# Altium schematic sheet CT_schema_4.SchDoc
size 235 x 238 mm
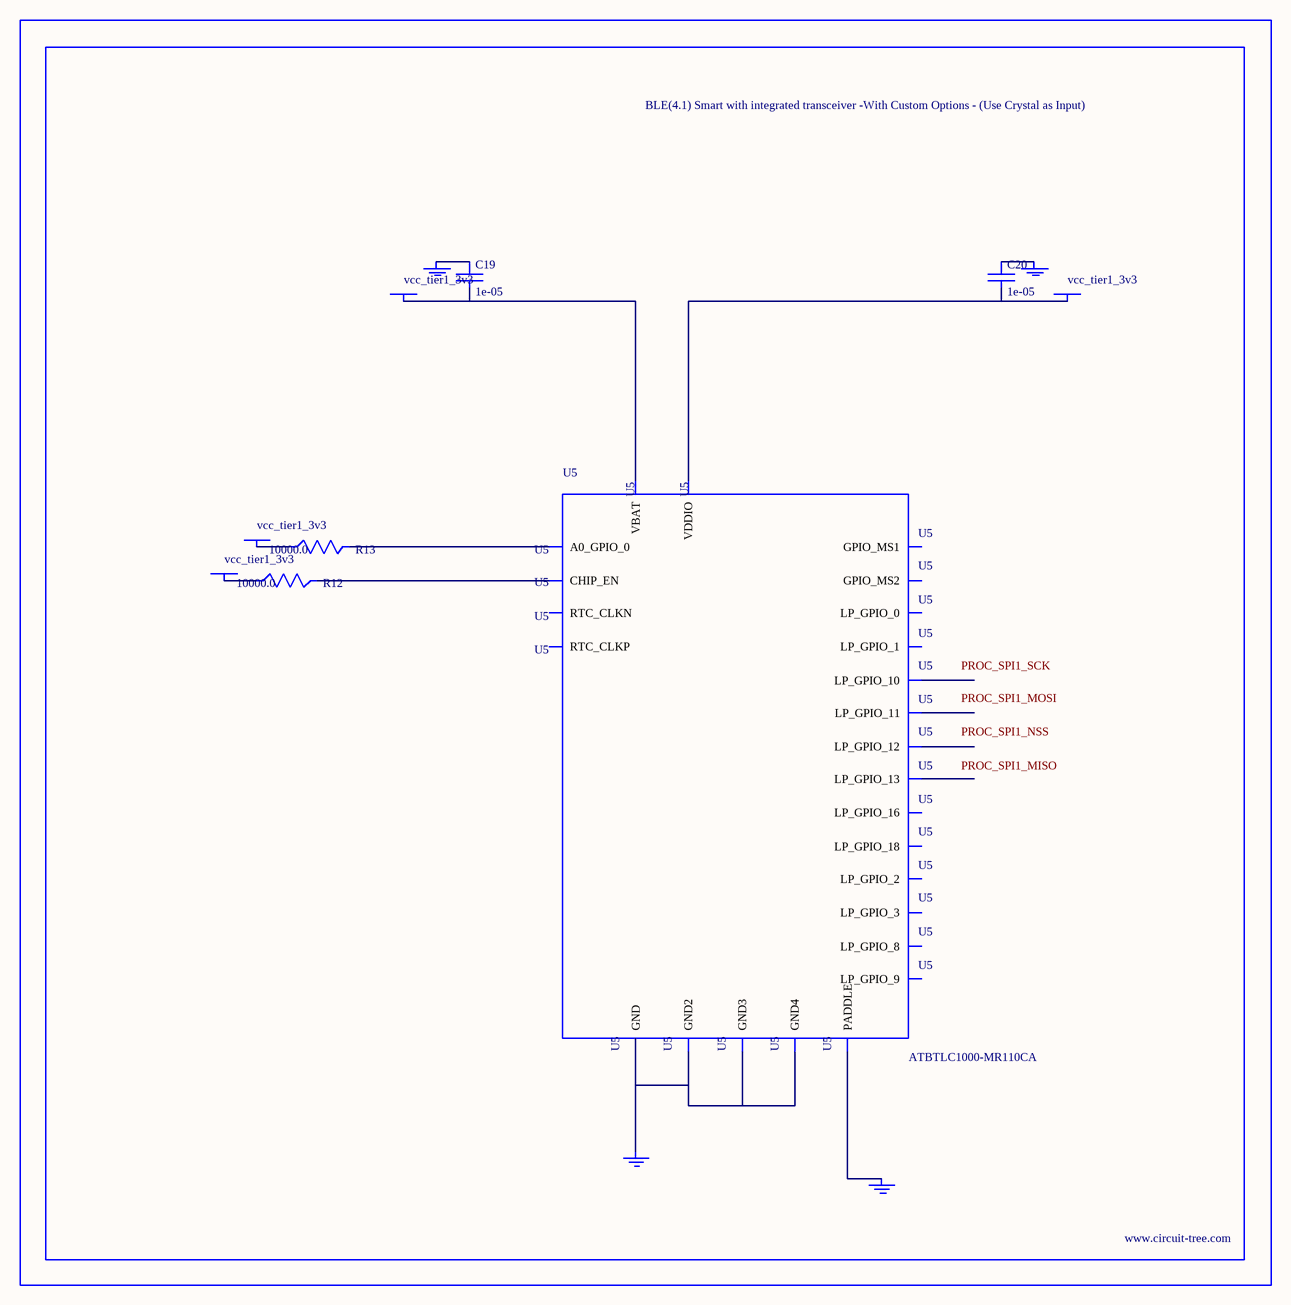
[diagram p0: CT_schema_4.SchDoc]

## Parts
BORDER3  (no value)
C19  1e-05  [C0805]
C20  1e-05  [C0805]
GND_INSTANCE_3_0  (no value)
GND_INSTANCE_3_1  (no value)
GND_INSTANCE_3_2  (no value)
GND_INSTANCE_3_3  (no value)
POWER_INSTANCE_3_0  vcc_tier1_3v3
POWER_INSTANCE_3_1  vcc_tier1_3v3
POWER_INSTANCE_3_2  vcc_tier1_3v3
POWER_INSTANCE_3_3  vcc_tier1_3v3
R12  10000.0  [R0603]
R13  10000.0  [R0603]
U5  ATBTLC1000-MR110CA  [ATBTLC1000-MR110CA]

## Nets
NetC19_1: C19.1 GND_INSTANCE_3_0.0(GND)
NetC19_2: C19.2 POWER_INSTANCE_3_0.0(PWR) U5.6(VBAT)
NetC20_1: C20.1 GND_INSTANCE_3_1.0(GND)
NetC20_2: C20.2 POWER_INSTANCE_3_3.0(PWR) U5.22(VDDIO)
NetGND_INSTANCE_3_2_0: GND_INSTANCE_3_2.0(GND) U5.25(PADDLE)
NetGND_INSTANCE_3_3_0: GND_INSTANCE_3_3.0(GND) U5.1(GND) U5.9(GND2) U5.13(GND3) U5.24(GND4)
NetPOWER_INSTANCE_3_1_0: POWER_INSTANCE_3_1.0(PWR) R12.1
NetPOWER_INSTANCE_3_2_0: POWER_INSTANCE_3_2.0(PWR) R13.1
NetR12_2: R12.2 U5.17(CHIP_EN)
NetR13_2: R13.2 U5.20(A0_GPIO_0)

Not connected (* = marked no-connect by the designer): U5 2(LP_GPIO_0) 3(LP_GPIO_1) 4(LP_GPIO_2) 5(LP_GPIO_3) 7(LP_GPIO_8) 8(LP_GPIO_9) 10(LP_GPIO_10) 11(LP_GPIO_11) 12(LP_GPIO_12) 14(LP_GPIO_13) 15(GPIO_MS1) 16(GPIO_MS2) 18(RTC_CLKP) 19(RTC_CLKN) 21(LP_GPIO_16) 23(LP_GPIO_18)

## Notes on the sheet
- Labels drawn without touching a wire or pin: PROC_SPI1_MISO, PROC_SPI1_MOSI, PROC_SPI1_NSS, PROC_SPI1_SCK

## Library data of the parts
BORDER3 = BORDER_PAGE3
C19 C20 = C0805C106K8RACTU
GND_INSTANCE_3_0-GND_INSTANCE_3_3 = GND
POWER_INSTANCE_3_0-POWER_INSTANCE_3_3 = PWR
R12 R13 = RC0603JR-0710KL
